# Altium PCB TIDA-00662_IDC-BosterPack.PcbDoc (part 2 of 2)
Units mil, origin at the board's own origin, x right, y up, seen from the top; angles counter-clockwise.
Board outline 2854.33 x 3248.03 mil, 4 copper layers (Top Layer, GND, +3.3V_Supply, Bottom Layer), stack 35.6 mil thick; 124 components, 110 nets, 427 pads, 203 vias.
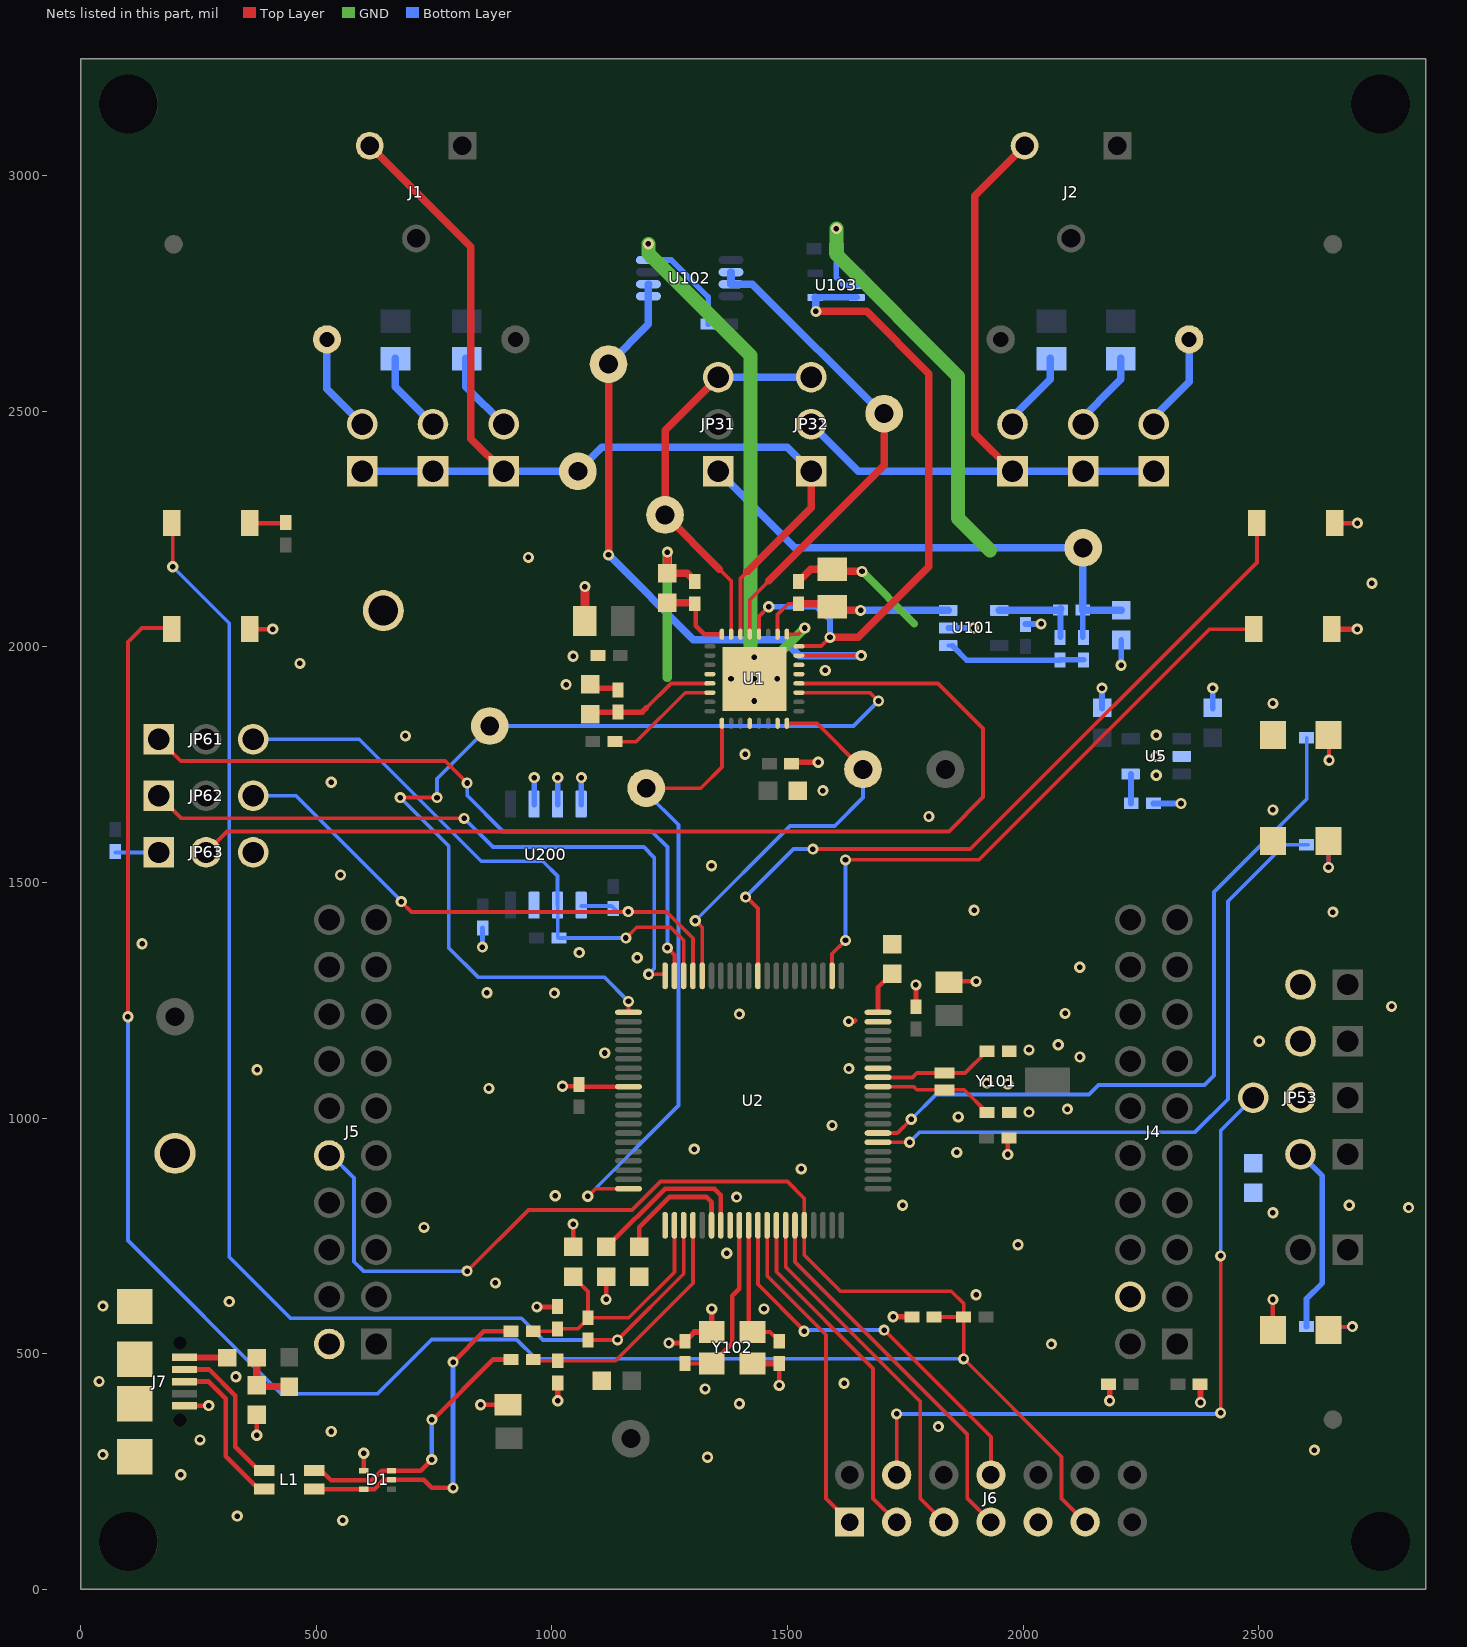
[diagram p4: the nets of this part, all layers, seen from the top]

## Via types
v1: diameter 23.62, hole 11.81, Top Layer to Bottom Layer, 200 vias
v2: diameter 23.62, hole 11.81, Top Layer to Bottom Layer, tented top, 2 vias
v3: diameter 23.62, hole 11.81, Top Layer to Bottom Layer, tented bottom, 1 vias

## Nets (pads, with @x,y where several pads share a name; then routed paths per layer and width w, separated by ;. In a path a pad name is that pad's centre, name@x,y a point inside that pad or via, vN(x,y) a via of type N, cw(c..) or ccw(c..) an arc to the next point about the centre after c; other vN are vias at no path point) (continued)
GND: C21.2 C22.1 C23.1 C24.2 C25.1 C28.1 C100.1 C101.1 C102.1 C103.1 C104.1 C105.1 C106.1 C107.2 C108.1 C109.2 C110.2 C111.2 C112.1 C113.2 C200.1 C201.2 C202.2 C203.1 C204.1 C205.2 C206.2 C207.2 C208.1 C209.2 C210.2 C211.2 C212.1 C213.2 C214.1 C215.2 C216.1 C217.1 D1.4 GND1.1 GND2.1 J4.4 J5.2 J6.9 J7.5 J7.6 J7.7 J7.8 J7.9 JP63.3 LED1.1 LED2.1 LED3.1 R208.1 S1.2 S2.1 S3.2 U1.4 U1.7 U1.13 U1.14 U1.17 U1.28 U1.33 U2.14 U2.19 U2.49 U2.61 U2.68 U5.2 U101.2 U102.4 U103.2 U200.2 U200.3 U200.4 U200.7 Y102.2 Y102.4 | length 4963.6
  Top Layer w8: U1.17@1498.43,2026.77 1523.11,2026.77 v1(1536.34,2040)
  Top Layer w10: J7.5@219.86,389.51 v1(271.51,389.51) ; S3.2@358.27,2037.52 v1(407.48,2037.52) ; v1(373.3,326.7) C28.1@373.3,370.2 ; D1.4@600.47,251.68 v1(600.47,288.53) ; v1(848.43,391.43) C24.2@907,391.43 ; v1(968,599) 1010.82,599 C207.2@1011.58,599.76 ; v1(1022.37,1067.52) 1053.75,1067.52 C210.2@1057.37,1071.14 1061.94,1066.58 U2.49@1162.4,1066.58 ; R208.1@1045,726.5 v1(1045,775) ; C102.1@1081.3,1920.2 C102.1@1089.17,1912.32 ; v1(1115,615) C203.1@1115,663.5 ; C103.1@1136.3,1912.32 C103.1@1140,1908.62 ; v1@1250,522.52 1278.75,522.52 C214.1@1282.37,526.14 ; v1(1482.37,432.52) C213.2@1482.37,478.9 ; v1(1629.49,1205) 1641.11,1205 1643,1206.89 ; C211.2@1772.37,1232.52 C211.2@1772.37,1236.14 v1(1772.37,1282.52) ; C215.2@1842.37,1288.39 1843.98,1290 v1(1900,1290) ; v1(1967.37,922.52) 1967.37,955.28 C209.2@1969.61,957.52 ; LED3.1@2529.89,550 v1(2529.89,614.89) ; S1.2@2659.26,2262.52 v1(2709.51,2262.52)
  Top Layer w12: v1(1012.37,400) C206.2@1012.37,437.52 ; C102.1@1089.17,1912.32 C103.1@1136.3,1912.32 ; C214.1@1282.37,526.14 1302.21,545.98 Y102.4@1339.06,545.98 v1@1339.06,595 ; Y102.2@1425.68,479.06 1425.83,478.9 C213.2@1482.37,478.9 ; C100.1@1508.62,1755 v1(1565,1755) ; v1(1724,578.31) C205.2@1765.13,578.31 ; C215.2@1842.37,1288.39 C215.2@1843.24,1287.52 ; v1@2183.47,396.22 C217.1@2183.47,437.52 ; v1(2376.39,396.22) C216.1@2376.39,437.52 ; S2.1@2659.26,2037.52 v1(2709,2037.52)
  Top Layer w16: v1(1245,2201) C104.1@1245,2156.5 1287.13,2156.5 C105.1@1305,2138.62 ; C107.2@1523,2138.62 1549.38,2165 C106.1@1595,2165 ; C106.1@1595,2160 v1(1658,2160)
  Top Layer w20: C109.2@1070,2055 v1(1070,2128)
  GND w16: v1(1658,2160) 1769,2049
  GND w20: 1245,1935 v1(1245,2201) ; 1471.34,1975 v1(1536.34,2040)
  GND w30: v1(1204.77,2855.23) 1204.77,2834.61 1421,2618.38 1421,1986.54 v1(1429.54,1978) ; v1(1603.62,2887.62) 1603.62,2832.38 1862,2574 1862,2273 1930,2205
  Bottom Layer w10: v1(852.37,1362.63) C200.1@852.37,1403.9
  Bottom Layer w12: U200.2@962.37,1664.8 v1(962.37,1722.52) ; U200.3@1012.37,1664.8 v1(1012.37,1722.52) ; U200.4@1062.37,1664.8 v1(1062.37,1722.52) ; v1(1204.77,2855.23) U102.4@1204.77,2820.91 1253.09,2820.91 1331.38,2742.62 C110.2@1331.38,2685 ; v1(1603.62,2887.62) C111.2@1603.62,2845 1603.62,2783.9 1620,2767.52 U103.2@1646.66,2767.52 ; U101.2@1840.87,2040 v1(1895,2040) ; C113.2@2005,2048.62 v1(2038,2048.62) ; C22.1@2167.37,1869.02 v1(2167.37,1912.52) ; v1(2208,1961) C112.1@2208,2014.5 ; C21.2@2275.99,1667.52 v1(2335,1667.52) ; C23.1@2402.37,1869.02 v1(2402.37,1912.52)
  other v1: 556,146 332,155 212,243 1330,280 47,285.77 2618.11,295.28 253,317 531.5,334.65 1820,345 1397.64,393.7 2183.47,400 1325,425 1620,437 39,441 329,451 2060,520 1248,522.52 1339,595 1450,595 47,600.77 314.96,610.24 1900,625 880,650 1371,713 1989,731 728.35,767.72 2530,799 2818.16,810 1744,815 2692,815 1392,832 1007,835 1529,892 1859,927 1302,934 1594.49,984.25 1862.37,1002.52 2012.37,1012.52 2094,1019 866.14,1062.99 1967.37,1072.52 1923,1074 374.02,1102.36 1630,1105 2120.32,1129.57 1112,1138 2012.37,1144.58 2074.42,1155.47 2501,1163 1397.64,1220.47 2089,1222 2782,1237 1005,1265 862,1266 2120,1320 1181.1,1340.2 1058,1351 130,1370 2657.48,1437.01 1896,1441 551.18,1515.75 1338.58,1535.43 1800,1640 2530,1654 1575,1695 531.5,1712.6 2282.37,1767.52 1410,1772 688.98,1811.02 2282.37,1812.52 2530,1880 1429.54,1885 1030,1920 1380,1932.28 1429.54,1932.28 1478,1932.28 1580,1950 465,1965 1045,1980 2740,2135 950,2190
  other v2: 2282.37,1727.52
JTAG_TCK: J6.7 U2.75 | length 802
  Top Layer w8: U2.75@1515.75,772.28 1515.75,694.25 1881.58,328.42 1881.58,192.52 J6.7@1931.58,142.52
JTAG_TDI: J6.3 U2.73 | length 735.5
  Top Layer w8: U2.73@1476.38,772.28 1476.38,673.62 1681.58,468.42 1681.58,192.52 J6.3@1731.58,142.52
JTAG_TDO: J6.1 U2.72 | length 702.2
  Top Layer w8: U2.72@1456.69,772.28 1456.69,664.89 1581.58,540 1581.58,192.52 J6.1@1631.58,142.52
JTAG_TMS: J6.5 U2.74 | length 768.7
  Top Layer w8: U2.74@1496.06,772.28 1496.06,683.94 1781.58,398.42 1781.58,192.52 J6.5@1831.58,142.52
JTAG_TST: J6.8 U2.71 | length 834.2
  Top Layer w8: U2.71@1437.01,772.28 1437.01,647.06 1535,549.06 v1(1535,547.52) ; v1(1705,550) 1931.58,323.42 J6.8@1931.58,242.52
  Bottom Layer w8: v1@1537.48,550 v1(1705,550)
JTAG_VCC_SENSE: J6.4 JP53.3 | length 1516.9
  Top Layer w8: J6.4@1731.58,242.52 v1@1731.58,368.42 ; v1(2419.21,374.21) v1(2419.21,707.52)
  Bottom Layer w8: v1(1731.58,372) v1@2417,372 ; v1@2415,370 v1@2417,372 ; v1(2419.21,374.21) v1@2417,372 ; v1(2419.21,707.52) 2419.21,973.7 JP53.3@2488.58,1043.07 ; JP53.3@2490.95,1043.07 JP53.3@2492.37,1041.65
LOL: J1.3 JP11.1 JP12.1 JP13.1 JP32.1 LOL.1 U1.22 | length 2196.8
  Top Layer w8: JP13.1@897.37,2372.52 JP13.1@897.57,2372.32 ; U1.22@1400.01,2026.77 1400.01,2145.01 1415,2160
  Top Layer w16: J1.3@613.16,3063.58 828,2848.74 828,2441.89 JP13.1@897.37,2372.52 ; 1415,2160 1550.01,2295.01 JP32.1@1550.01,2372.52
  Bottom Layer w16: JP11.1@611.19,2372.72 JP12.1@761.19,2372.72 ; JP12.1@762.37,2372.52 JP13.1@897.37,2372.52 LOL.1@1055,2372.52 1106,2423.52 1499.01,2423.52 JP32.1@1550.01,2372.52
LOR: JP31.3 JP32.3 LOR.1 U1.23 | length 847.6
  Top Layer w8: 1355,2165 1380.32,2139.68 U1.23@1380.32,2026.77
  Top Layer w16: JP31.3@1353.16,2572.52 1240,2459.36 LOR.1@1240,2280 1355,2165
  Bottom Layer w16: JP31.3@1353.16,2572.52 JP32.3@1550.01,2572.52
MCU_MCLK: MCLK.1 U1.1 U2.60 | length 1339
  Top Layer w8: v1(1076,834) 1092.04,850.04 U2.60@1162.4,850.04 ; MCLK.1@1200,1700 1315.64,1700 1360.64,1745 U1.1@1360.64,1837.8
  Bottom Layer w8: v1(1076,834) 1268.26,1026.26 1268.26,1622.26 1200,1690.52 MCLK.1@1200,1700
MCU_RST: C205.1 J5.10 J6.11 R202.1 S3.1 U2.76 | length 5789.7
  Top Layer w8: v1(100,1215) 100,2010 130,2040 190.43,2040 S3.1@192.91,2037.52 ; v1(820,675) 950,805 1170,805 1230,865 1499.89,865 1535.43,829.46 U2.76@1535.43,772.28 1535.43,709.46 1612.37,632.52 1847.37,632.52 1873.75,606.14 R202.1@1873.75,577.52 ; C205.1@1810.99,577.52 R202.1@1873.75,577.52 ; J6.11@2131.58,142.52 2081.58,192.52 2081.58,281.06 v1(1873.75,488.9) R202.1@1873.75,577.52
  Bottom Layer w8: v1(100,1215) 100,740 425,415 630,415 745,530 924.8,530 965.91,488.9 v1(1873.75,488.9) ; J5.10@529.54,922.99 580,872.53 580,695 600,675 v1(820,675)
MCU_SCL: JP61.3 R201.1 U2.38 U200.6 | length 1257.3
  Top Layer w8: v1(1157,1382) 1180,1405 1251.52,1405 1279.53,1376.99 U2.38@1279.53,1301.81
  Bottom Layer w8: JP61.3@365.75,1803.86 591.14,1803.86 850,1545 980.52,1545 1012,1513.52 U200.6@1012,1451.72 ; R201.1@1012.37,1382.52 U200.6@1012.37,1450.24 ; R201.1@1014.62,1382 v1(1157,1382)
MCU_SDA: JP62.3 R200.1 U2.37 U200.5 | length 1244.6
  Top Layer w8: v1(680,1459.17) 701.79,1437.38 1243.56,1437.38 1299.21,1381.72 U2.37@1299.21,1301.81
  Bottom Layer w8: JP62.3@365.75,1683.78 456.96,1683.78 680,1460.74 v1(680,1459.17) ; U200.5@1062.37,1450.24 1126.03,1450.24 1138.89,1437.38 1139.51,1438 v1(1162,1438)
NetC21_1: C21.1 U5.4 | length 62.8
  Bottom Layer w12: U5.4@2228.24,1730.12 2228.75,1729.6 C21.1@2228.75,1667.52
NetC25_2: C25.2 JP1.2 JP51.2 JP52.2 JP53.2 R20.1 | length 409.8
  Bottom Layer w12: JP1.2@2590.95,922.99 JP1.2@2588.58,922.99 2635,876.58 2635,650 2601.38,616.38 R20.1@2601.38,557.19 ; JP53.2@2590.95,1034.61 JP53.2@2590.95,1043.07
NetC28_2: C28.2 L2.2 L3.1 | length 135.4
  Top Layer w10: C28.2@373.37,431.52 C28.2@374.39,430.5
  Top Layer w15: C28.2@373.37,431.52 L2.2@373.37,496.52 ; C28.2@374.39,430.5 L3.1@443.37,430.5
NetC102_2: C102.2 C103.2 U1.29 | length 280.8
  Top Layer w8: 1200,1870.08 1252.36,1922.44 U1.29@1335.05,1922.44
  Top Layer w12: C102.2@1081.3,1857.2 1085.47,1861.38 C103.2@1140,1861.38 1191.3,1861.38 1200,1870.08
NetC104_2: C104.2 C105.2 U1.24 | length 170.4
  Top Layer w10: C105.2@1305,2091.38 1305,2045 1323.23,2026.77 U1.24@1360.64,2026.77
  Top Layer w12: C105.2@1302.87,2093.5 C105.2@1305,2091.38
  Top Layer w16: C104.2@1245,2093.5 C105.2@1302.87,2093.5
NetC106_2: C106.2 C107.1 U1.18 U101.3 | length 419.1
  Top Layer w8: U1.18@1478.75,2026.77 1478.75,2068.75 1501.38,2091.38 C107.1@1525,2091.38
  Top Layer w12: C106.2@1588.62,2091.38 C106.2@1595,2085
  Top Layer w16: C107.1@1525,2091.38 C106.2@1588.62,2091.38 ; C106.2@1593.62,2081.38 1597.6,2077.4 v1(1655,2077.4)
  Bottom Layer w16: v1(1655,2077.4) U101.3@1840.87,2077.4
NetC112_2: C112.2 JP31.1 R100.1 R106.1 VRef.1 | length 1114.4
  Bottom Layer w8: R100.1@2126.62,2021 R100.1@2128,2019.62
  Bottom Layer w12: R100.1@2126.62,2021 R106.1@2126.62,2078
  Bottom Layer w16: JP31.1@1353.16,2372.52 1515.68,2210 VRef.1@2127.37,2210 2126.62,2209.25 R106.1@2126.62,2078 2207.5,2078 C112.2@2208,2077.5
NetC114_1: C114.1 R106.2 U101.4 | length 193.7
  Bottom Layer w8: C114.1@2078,2019.62 C114.1@2079.38,2021
  Bottom Layer w12: C114.1@2079.38,2021 R106.2@2079.38,2081
  Bottom Layer w16: U101.4@1949.13,2077.4 2075.78,2077.4 R106.2@2079.38,2081
NetC114_2: C114.2 R100.2 U101.1 | length 300.1
  Bottom Layer w8: U101.1@1840.87,2002.6 U101.1@1849.4,2002.6
  Bottom Layer w12: U101.1@1849.4,2002.6 1880.62,1971.38 C114.2@2078,1971.38 ; C114.2@2078,1972.38 R100.2@2128,1972.38
NetC201_1: C201.1 U2.12 Y101.2 | length 254
  Top Layer w8: U2.12@1691.93,1066.58 1767.53,1066.58 1774.26,1059.84 Y101.2@1833.16,1059.84 1874.86,1059.84 C201.1@1923.12,1011.58
NetC202_1: C202.1 U2.13 Y101.1 | length 254.1
  Top Layer w8: U2.13@1691.93,1086.26 1765.32,1086.26 1774.34,1095.28 Y101.1@1833.16,1095.28 1876.82,1095.28 C202.1@1923.12,1141.58
NetC203_2: C203.2 U2.67 | length 362.8
  Top Layer w10: C203.2@1116.5,726.5 1240,850 1344.83,850 1358.27,836.56 U2.67@1358.27,772.28
NetC204_2: C204.2 U2.20 | length 96.9
  Top Layer w10: U2.20@1691.93,1224.06 1691.93,1277.08 1712.37,1297.52 C204.2@1727.37,1297.52
NetC206_1: C206.1 R206.1 U2.64 | length 531.3
  Top Layer w8: R206.1@960.21,487.52 962.96,484.76 1134.61,484.76 1299.21,649.36 U2.64@1299.21,772.28
NetC207_1: C207.1 R204.1 R205.2 R208.2 U2.62 | length 551.4
  Top Layer w8: R204.1@960.21,547.52 1006.58,547.52 C207.1@1011.58,552.52 1054.52,552.52 1078,576 1163,576 1259.84,672.84 U2.62@1259.84,772.28 ; R208.2@1045,663.5 1076.58,631.92 R205.2@1076.58,576.14
NetC208_2: C208.2 U2.66 | length 275.5
  Top Layer w10: C208.2@1185,726.5 1185,767.99 1249.53,832.52 1327.37,832.52 1338.58,821.31 U2.66@1338.58,772.28
NetC213_1: C213.1 U2.70 Y102.3 | length 294.7
  Top Layer w8: Y102.3@1425.68,545.98 1462.53,545.98 C213.1@1482.37,526.14
  Top Layer w10: U2.70@1417.32,772.28 1417.32,554.34 Y102.3@1425.68,545.98
NetC214_2: C214.2 U2.69 Y102.1 | length 374.2
  Top Layer w8: C214.2@1282.37,478.9 1282.53,479.06 Y102.1@1339.06,479.06
  Top Layer w10: Y102.1@1339.06,479.06 1382.37,522.36 1382.37,622.52 1397.64,637.79 U2.69@1397.64,772.28
NetCh1_1: Ch1.1 U1.15 U102.1 U102.2 | length 1367.6
  Top Layer w8: U1.15@1524.02,1981.5 v1(1656.5,1981.5)
  Top Layer w16: v1(1120,2195) Ch1.1@1120,2600
  Bottom Layer w16: v1(1120,2195) 1300,2015 1490.91,2015 1524.42,1981.5 v1(1656.5,1981.5) ; Ch1.1@1120,2600 1204.77,2684.77 U102.1@1204.77,2744.13 U102.2@1204.77,2769.72 U102.2@1205,2769.5
NetCh2_1: Ch2.1 U1.21 U102.6 U102.7 | length 1063.3
  Top Layer w8: U1.21@1419.69,2026.77 1419.69,2099.69 1460,2140
  Top Layer w16: 1460,2140 1705,2385 Ch2.1@1705,2495
  Bottom Layer w16: U102.6@1379.97,2795.32 U102.7@1379.97,2769.72 ; U102.7@1380.24,2770 U102.7@1379.97,2769.72 ; Ch2.1@1705,2480 1705,2490 1425.28,2769.72 U102.7@1379.97,2769.72
NetJ2_3: J2.3 JP21.1 JP22.1 JP23.1 JP32.2 | length 1528.9
  Top Layer w16: JP23.1@1977.37,2372.52 1897.37,2452.52 1897.37,2957.8 J2.3@2003.15,3063.58 ; J2.3@2008.15,3058.58 J2.3@2013.16,3063.58
  Bottom Layer w16: JP32.2@1550.01,2472.52 1650.01,2372.52 JP21.1@2262.37,2372.52
NetJ7_1: J7.1 L2.1 | length 92.7
  Top Layer w12: J7.1@219.86,491.87 312.36,491.87 L2.1@312.49,492
NetJ7_2: J7.2 L1.3 | length 322
  Top Layer w10: J7.2@219.86,466.28 272.72,466.28 328,411 328,301.89 377.68,252.21 L1.3@389.22,252.21
NetJ7_3: J7.3 L1.2 | length 335.3
  Top Layer w10: J7.3@219.86,440.69 271.31,440.69 307.37,404.63 307.37,282.52 377.05,212.84 L1.2@389.22,212.84
NetJP11_2: JP11.2 R101.2 | length 211.1
  Bottom Layer w16: R101.2@522.37,2652.52 522.37,2547.52 JP11.2@597.37,2472.52
NetJP12_2: JP12.2 R102.2 | length 173.1
  Bottom Layer w16: R102.2@667.37,2612.52 667.37,2552.52 JP12.2@747.37,2472.52
NetJP13_2: JP13.2 R103.2 | length 173.1
  Bottom Layer w16: R103.2@817.37,2612.52 817.37,2552.52 JP13.2@897.37,2472.52
NetJP21_2: JP21.2 R111.2 | length 217.3
  Bottom Layer w16: JP21.2@2262.37,2472.52 2352.37,2562.52 R111.2@2352.37,2652.52
NetJP22_2: JP22.2 R112.2 | length 179.4
  Bottom Layer w16: JP22.2@2112.37,2472.52 2207.37,2567.52 R112.2@2207.37,2612.52
NetJP23_2: JP23.2 R113.2 | length 179.4
  Bottom Layer w16: JP23.2@1962.37,2472.52 2057.37,2567.52 R113.2@2057.37,2612.52
NetJP63_1: JP63.1 R105.2 | length 92.9
  Bottom Layer w8: R105.2@73,1563.38 73.32,1563.7 JP63.1@165.75,1563.7
NetLED1_2: LED1.2 R203.1 | length 102
  Top Layer w8: LED1.2@2648,1813 2649.24,1811.76 v1(2649.24,1759.24)
  Bottom Layer w8: v1(2649.24,1759.24) R203.1@2649.24,1807
NetLED2_2: LED2.2 R207.1 | length 105.5
  Top Layer w8: v1(2648,1532) LED2.2@2648,1588
  Bottom Layer w8: v1(2648,1532) 2648,1576.38 R207.1@2651.62,1580
NetLED3_2: LED3.2 R20.2 | length 104
  Top Layer w8: LED3.2@2648,550 2655.19,557.19 v1(2698.81,557.19)
  Bottom Layer w8: R20.2@2648.62,557.19 v1(2698.81,557.19)
NetR104_2: R104.2 U1.30 | length 244.5
  Top Layer w8: R104.2@1133.62,1798.79 1178.79,1798.79 1282.76,1902.76 U1.30@1335.05,1902.76
NetR203_2: R203.2 U2.7 | length 1562.1
  Top Layer w8: U2.7@1691.93,968.15 1733,968.15 v1(1762.37,997.52)
  Bottom Layer w8: v1(1762.37,997.52) 1814.85,1050 2140,1050 2160,1070 2385,1070 2405,1090 2405,1480 2602,1677 R203.2@2602,1807
NetR205_1: R205.1 S4.1 U2.63 | length 2868.9
  Top Layer w8: S4.1@192.91,2262.52 195,2260.43 v1(195,2170) ; R205.1@1076.58,528.9 1138.9,528.9 v1(1139,529) 1279.53,669.53 U2.63@1279.53,772.28
  Bottom Layer w8: v1(195,2170) 315,2050 315,705 445,575 935,575 981,529 v1(1139,529)
NetR207_2: R207.2 U2.6 | length 1420.1
  Top Layer w8: U2.6@1691.93,948.47 v1(1759.11,948.47)
  Bottom Layer w8: v1(1759.11,948.47) 1780.64,970 2365,970 2435,1040 2435,1460 2555,1580 R207.2@2604.38,1580
NetR209_1: R209.1 S4.2 | length 77.2
  Top Layer w10: S4.2@358.27,2262.52 433.9,2262.52 R209.1@435,2263.62
NetS1_1: S1.1 U2.30 | length 1641.8
  Top Layer w8: v1(1411,1469) 1413,1469 1437.01,1444.99 U2.30@1437.01,1301.81 ; v1(1553.81,1570.81) 1887.81,1570.81 2496.06,2179.06 S1.1@2496.06,2262.52
  Bottom Layer w8: v1(1411,1469) 1512.81,1570.81 v1(1553.81,1570.81)
NetS2_2: S2.2 U2.22 | length 1331.7
  Top Layer w8: U2.22@1594.49,1301.81 1594.49,1348.49 v1(1623,1377) ; v1(1623,1548) 1906.05,1548 2343.46,1985.41 ; 2343.46,1985.46 2395.52,2037.52 S2.2@2493.91,2037.52
  Bottom Layer w8: v1(1623,1377) v1(1623,1548)
NetU1_16: U1.16 U1.20 U103.3 U103.4 | length 1407.6
  Top Layer w8: U1.20@1439.38,2026.77 1439.38,2064.38 v1(1460,2085) ; U1.16@1530.57,2001.55 1571.55,2001.55 v1(1590,2020)
  Top Layer w16: v1(1560,2712) 1668,2712 1800,2580 1800,2170 1650,2020 v1(1590,2020)
  Bottom Layer w12: v1(1460,2085) 1561.69,2085 1590,2056.69 v1(1590,2020)
  Bottom Layer w14: U103.4@1558.08,2741.93 U103.3@1646.66,2741.93
  Bottom Layer w16: U103.4@1558.71,2741.41 1560,2740.12 v1(1560,2712)
SPI_MISO: MISO.1 U1.11 U2.41 | length 2111.7
  Top Layer w8: v1(678,1680) v1(756,1680) ; v1(1162.37,1247.52) 1162.37,1228.98 U2.41@1164.77,1226.57 ; U1.11@1524.02,1902.76 1675.24,1902.76 v1(1693,1885)
  Bottom Layer w8: v1(678,1680) 781,1577 781,1361 843,1299 1110.89,1299 v1(1162.37,1247.52) ; v1(756,1680) 756,1720 MISO.1@868,1832 1640,1832 v1(1693,1885)
SPI_MOSI: JP62.1 U2.40 | length 1393.7
  Top Layer w8: JP62.1@165.75,1683.78 213.53,1636 v1(813.61,1636) ; v1(1205,1305) 1239.49,1305 U2.40@1240.16,1304.33
  Bottom Layer w8: v1(813.61,1636) 874.61,1575 1195,1575 1216.81,1553.19 1216.81,1316.81 v1(1205,1305)
SPI_SCLK: SCLK.1 U1.8 U2.36 | length 849.2
  Top Layer w8: v1(1304.19,1418.81) 1318.9,1404.1 U2.36@1318.9,1301.81 ; U1.8@1498.43,1837.8 1562.2,1837.8 SCLK.1@1660,1740
  Bottom Layer w8: v1(1304.19,1418.81) 1505.38,1620 1600,1620 1660,1680 SCLK.1@1660,1740
SPI_SELECT: JP63.2 U1.12 | length 2274.3
  Top Layer w8: JP63.2@265.75,1563.7 310.43,1608.38 1842.38,1608.38 1915,1681 1915,1827 1819.56,1922.44 U1.12@1524.02,1922.44
SPI_SS~: JP61.1 U2.39 | length 1469
  Top Layer w8: JP61.1@165.75,1803.86 212.09,1757.52 773.48,1757.52 v1(820,1711) ; v1(1245,1361) 1259.84,1346.16 U2.39@1259.84,1301.81
  Bottom Layer w8: v1(820,1711) 820,1684.42 896.04,1608.38 1211.62,1608.38 1245,1575 v1(1245,1361)
USB_DATA+: D1.2 D1.5 L1.1 R204.2 | length 738.3
  Top Layer w10: L1.1@506.84,212.84 L1.1@495.52,212.84 496.04,212.31 D1.5@600.47,212.31 623.31,212.31 643,232 D1.2@659.53,232 728,232 745,215 v1(790,215) ; v1(790,482) 855.52,547.52 R204.2@912.96,547.52
  Bottom Layer w10: v1(790,215) v1(790,482)
USB_DATA-: D1.3 L1.4 R206.2 | length 582.2
  Top Layer w10: L1.4@495.52,252.21 509.79,252.21 531,231 618,231 638.68,251.68 D1.3@659.53,251.68 721.54,251.68 v1(744.85,275) ; v1(745,360) 747.48,360 875,487.52 R206.2@912.96,487.52
  Bottom Layer w10: v1(744.85,275) 744.85,359.85 v1(745,360)
pads on no net: FID1.1 FID2.1 FID3.1 J6.6 J6.10 J6.12 J6.13 J6.14 J7.4 J7.MH1 J7.MH2 U1.2 U1.3 U1.5 U1.19 U1.25 U1.27 U2.5 U2.8 U2.9 U2.10 U2.15 U2.26 U2.32 Y101.
copper on no net:
  other v1: 1062.37,377.52

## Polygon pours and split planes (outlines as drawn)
GND on Bottom Layer "U103_GND" (solid, remove dead copper, pour order 14): 1616.99,2920 1584,2920 1571,2907 1571,2899 1571,2760 1588,2743 1589,2742 1683,2742 1697,2756 1698,2757 1698,2783 1683.48,2797.52 1630.37,2797.52 1630.37,2886.28 1630.37,2907
GND on Bottom Layer "U102_GND" (solid, remove dead copper, pour order 13): 1165,2882 1153,2870 1153,2819 1170,2802 1245,2802 1279,2768 1279,2669 1296,2652 1346,2652 1362.68,2668.68 1362.68,2750.23 1362.68,2760.32 1241,2882
GND on Bottom Layer "BotLayer_GND" (solid, remove dead copper, pour order 22): 19.68,2322.84 19.68,196.85 196.85,196.85 196.85,19.68 2657.48,19.68 2657.48,196.85 2834.65,196.85 2834.65,2322.83 1992.83,2322.83 1640,1970 1493,1970 1493,1995 1358,1995 1358,1955 1180,1955 1120,2015 1120,2130 927.16,2322.84
+5V_USB on Bottom Layer "+5V_USB" (solid, remove dead copper, pour order 17): 2477.37,1700 2317.37,1700 2317.37,1712.52 2317.37,1847.52 2477.37,1847.52
+3.3V_LDO on Bottom Layer "+3.3V_LDO" (solid, remove dead copper, pour order 18): 2247.37,1847.52 2247.37,1722.52 2062.37,1722.52 2062.37,1847.52
NetC25_2 on Bottom Layer "+3.3V_BottomLayer" (solid, remove dead copper, pour order 16): 2560,1345 2550.35,1345 2537,1331.64 2537,1016.02 2504.98,984 2464,984 2441.33,961.33 2441.33,948.67 2441.33,904.09 2441.33,883.67 2460,865 2615,865 2640,889.84 2641.81,891.65 2641.81,1330 2626.81,1345
GND on GND "GNDLayer" (solid, remove dead copper, pour order 23): 19.68,2322.83 19.68,196.85 196.85,196.85 196.85,19.68 2657.48,19.68 2657.48,196.85 2834.65,196.85 2834.65,2322.83 1992.83,2322.83 1640,1970 1500,1970 1500,2005 1360,2005 1360,1955 1180,1955 1120,2015 1120,2130 1096,2154 927.17,2322.83
+3.3V_SUPPLY on +3.3V_Supply "+3.3V_Supply" (solid, remove dead copper, pour order 24): 19.68,2322.83 19.68,196.85 196.85,196.85 196.85,19.68 2657.48,19.68 2657.48,196.85 2834.65,196.85 2834.65,2322.83 1995.31,2322.83 1995,2322.52 1642.48,1970 1640,1970 1515,1970 1510,1975 1510,2010 1365,2010 1360,2005 1360,1955 1180,1955 1120,2015 1120,2130 1120,2130.2 927.68,2322.52
NetC25_2 on +3.3V_Supply "+3.3V Selection" (solid, remove dead copper, pour order 15): 2527.96,1323.39 2527.96,869.65 2550.09,847.52 2617.37,847.52 2627.37,847.52 2647.37,867.52 2647.37,1327.52 2629.89,1345 2549.57,1345
GND on Top Layer "TopLayer_GND" (solid, remove dead copper, pour order 21): 19.98,2322.83 928.16,2322.84 1105,2146 1120,2131 1120,2015 1180,1955 1350,1955 1350,2010 1510,2010 1510,1970 1640,1970 1992.83,2322.83 2834.64,2322.84 2834.63,196.85 2657.47,196.85 2657.47,19.68 196.84,19.68 196.84,196.85 19.68,196.85

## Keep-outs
Keep-Out Layer:
  lines w10: -5,0 ccw(c0,0) 0,-5 ; -5,0 ccw(c0,0) 0,-5 ; -5,0 -5,3248.03 ; -5,3248.03 cw(c0,3248.03) 0,3253.03 ; -5,3248.03 cw(c0,3248.03) 0,3253.03 ; 0,-5 2854.33,-5 ; 0,3253.03 2854.33,3253.03 ; 2854.33,-5 ccw(c2854.33,0) 2859.33,0 ; 2854.33,-5 ccw(c2854.33,0) 2859.33,0 ; 2854.33,3253.03 cw(c2854.33,3248.03) 2859.33,3248.03 ; 2854.33,3253.03 cw(c2854.33,3248.03) 2859.33,3248.03 ; 2859.33,0 2859.33,3248.03
  text ".Layer_Name" at 577,-858.49 h60

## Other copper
Top Layer:
  text ".Layer_Name" at 577,-858.49 h60
Bottom Layer:
  text ".Layer_Name" at 577,-858.49 h60

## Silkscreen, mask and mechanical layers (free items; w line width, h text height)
Top Overlay:
  drawing of 1651 lines, arcs and shapes, not listed
  text "Z-Domain Booster Pack" at 1836,3131 h40 r180
  text "V1.0" at 1279,3053 h40 r180
  text "TIDA-00662" at 1730,3053 h40 r180
  text "SCL/SS" at 603,1818 h30 r180
  text "SDA/MOSI" at 651,1696 h30 r180
  text "I2C/SPI" at 616,1578 h30 r180
  text ".Layer_Name" at 577,-858.49 h60
Bottom Overlay:
  text ".Layer_Name" at 577,-858.49 h60
Top Paste:
  text ".Layer_Name" at 577,-858.49 h60
Bottom Paste:
  text ".Layer_Name" at 577,-858.49 h60
Top Solder:
  text ".Layer_Name" at 577,-858.49 h60
  text ".Layer_Name" at 577,-858.49 h60
Bottom Solder:
  text ".Layer_Name" at 577,-858.49 h60
Drill Guide:
  text ".Layer_Name" at 577,-858.49 h60
M1 Board Outline:
  the board outline again, w10
  text ".Layer_Name" at 577,-858.49 h60
M2 Board Dimensions:
  rectangle: 125,-400 500,-275
  rectangle: 0,-275 125,-150
  lines w3.94: 2.37,2.52 2.37,3250.55 2856.7,3250.55 2856.7,2.52 2.37,2.52
  lines w7: 0,-275 1000,-275 ; 125,-400 125,-150 ; 250,-400 250,-150 ; 500,-400 500,-150 ; 750,-400 750,-150 ; 0,-400 0,-150 1000,-150 1000,-400 0,-400
  text ".Layer_Name" at 577,-858.49 h60
M3 3D STEP Top:
  text ".Layer_Name" at 577,-858.49 h60
M4 3D STEP Bottom:
  text ".Layer_Name" at 577,-858.49 h60
M5 Assembly Top:
  lines w10: -292,-930.17 6308,-930.17 ; -292,-726.83 6310,-726.83 ; -292,-523.5 -292,-1133.5 3713,-1133.5 6310,-1133.5 6310,-523.5 -291.5,-523.5 -291.5,-1133.5 1284,-1133.5 ; 2173,-1133.5 2173,-523.5 ; 3440,-726.83 3440,-523.5 ; 4280,-726.83 4280,-523.5 ; 4902,-1140 4902,-937.17
  text "COMPONENTS MARKED 'DNP' SHOULD NOT BE POPULATED." at 1153.5,-318.5 h60
  text "ASSEMBLY VARIANT:" at 1153,-434 h60
  text ".VariantName" at 2189,-434 h60
  text "PCB VIEWED FROM TOP SIDE" at -228.5,-655.67 h60
  text "BOARD #:" at 2248,-655.67 h60
  text ".PRJ_Number" at 2793.5,-655.67 h60
  text "REV:" at 3638,-655.67 h60
  text ".PCB_Rev" at 3929.5,-655.67 h60
  text "SVN REV:" at 4476,-655.67 h60
  text ".VersionControl_RevNumber" at 4982,-655.67 h60
  text "TID #:" at 2248,-859 h60
  text ".TID" at 2793.5,-859 h60
  text "PLOT NAME =" at -228.5,-1064.34 h60
  text ".plot_File_Name" at 577,-1064.34 h60
  text "GENERATED    :" at 2250,-1064.34 h60
  text ".Print_Date" at 3119.5,-1064.34 h60
  text ".Print_Time" at 3848.5,-1064.34 h60
  text "TEXAS INSTRUMENTS" at 5113,-1064.34 h60
M6 Assembly Bottom:
  lines w10: -292.5,-727.33 6309.5,-727.33 ; -290.5,-930.67 6309.5,-930.67 ; 1115.5,-1140.5 1115.5,-937.67 ; 1737.5,-727.33 1737.5,-524 ; 2577.5,-727.33 2577.5,-524 ; 3844.5,-1134 3844.5,-524 ; 4733.5,-1134 6309,-1134 6309,-524 -292.5,-524 -292.5,-1134 2304.5,-1134 6309.5,-1134 6309.5,-524
  text "COMPONENTS MARKED 'DNP' SHOULD NOT BE POPULATED." at 6102,-318 h60
  text ".VariantName" at 5058,-434 h60
  text "ASSEMBLY VARIANT:" at 6097,-434 h60
  text ".VersionControl_RevNumber" at 1035.5,-656.17 h60
  text "SVN REV:" at 1541.5,-656.17 h60
  text ".PCB_Rev" at 2088,-656.17 h60
  text "REV:" at 2379.5,-656.17 h60
  text ".PRJ_Number" at 3224,-656.17 h60
  text "BOARD #:" at 3769.5,-656.17 h60
  text "PCB VIEWED FROM BOTTOM SIDE" at 6246,-656.17 h60
  text ".TID" at 3224,-859.5 h60
  text "TID #:" at 3769.5,-859.5 h60
  text "TEXAS INSTRUMENTS" at 904.5,-1064.84 h60
  text ".Print_Time" at 2169,-1064.84 h60
  text ".Print_Date" at 2898,-1064.84 h60
  text "GENERATED    :" at 3767.5,-1064.84 h60
  text ".plot_File_Name" at 5440.5,-1064.84 h60
  text "PLOT NAME =" at 6246,-1064.84 h60
M9 Title Sheet:
  drawing of 57 lines, arcs and shapes, not listed
  text "1" at 739.84,8036.5 h70
  text "2" at 3235.5,8036.5 h70
  text "3" at 5724.84,8036.5 h70
  text "4" at 8231.51,8036.5 h70
  text "5" at 10730.5,8036.5 h70
  text "6" at 13235.5,8036.5 h70
  text "A" at -416.5,6893.5 h70
  text "A" at 14383.5,6893.5 h70
  text "B" at -416.5,4513.5 h70
  text "B" at 14383.5,4513.5 h70
  text "C" at -416.5,2138.5 h70
  text "C" at 14383.5,2138.5 h70
  text "PROJECT TITLE:" at 11343.5,277.5 h45
  text ".PRJ_Title" at 11393.5,144.17 h70
  text "DESIGNED FOR:" at 11343.5,-23.5 h45
  text ".PRJ_Customer" at 11393.5,-163.5 h70
  text "D" at -416.5,-231.5 h70
  text "D" at 14383.5,-231.5 h70
  text "FILE NAME:" at 11343.5,-323.5 h45
  text ".PCB_File_Name_No_Path" at 11393.5,-443.5 h70
  text "Texas Instruments (TI) and/or its licensors do not warrant the accuracy or completeness of this specification" at 6374,-605.34 h45
  text "ENGINEER:" at 11343.5,-613.5 h45
  text "LAYOUT BY:" at 12848.5,-613.5 h45
  text "or any information contained therein. TI and/or its licensors do not warrant that this design will meet" at 6329.01,-718 h45
  text ".PRJ_Engineer" at 11393.5,-768.49 h70
  text ".PCB_Layout" at 12899,-768.49 h70
  text "the specifications, will be suitable for your application or fit for any particular purpose, or will operate in" at 6329.01,-830.67 h45
  text ".Layer_Name" at 577,-858.49 h60
  text "ALTIUM DESIGNER VERSION:" at 12848.5,-923.5 h45
  text "an implementation. TI and/or its licensors do not warrant that the design is production worthy. You should" at 6329.01,-943.33 h45
  text "completely validate and test your design implementation to confirm the system functionality for your application." at 6374,-1056 h45
  text ".print_Scale" at 11393.5,-1056.83 h70
  text ".Application_BuildNumber" at 12899,-1056.83 h70
  text "1" at 739.84,-1263.5 h70
  text "2" at 3235.5,-1263.5 h70
  text "3" at 5724.84,-1263.5 h70
  text "4" at 8231.51,-1263.5 h70
  text "5" at 10730.5,-1263.5 h70
  text "6" at 13235.5,-1263.5 h70
M10 Fab Notes:
  drawing of 185 lines, arcs and shapes, not listed
  text "DESIGN INFORMATION" at 12381.02,5910 h60
  text "MIN. TRACK WIDTH:" at 11736.46,5730 h60
  text "8" at 12832.7,5730 h60
  text "MIL" at 12987.46,5730 h60
  text "MIN. CLEARANCE:" at 11736.46,5598 h60
  text "MIL" at 12987.46,5598 h60
  text "6" at 12835,5590 h60
  text "MIN. VIA PAD SIZE:" at 11736.46,5466 h60
  text "24" at 12802.71,5466 h60
  text "MIL" at 12987.46,5466 h60
  text "0.05mm (2MIL)" at 12431.46,5324.29 h60
  text "MINIMUM ANNULAR RING" at 11407.23,5320 h60
  text "EXTERNAL" at 13139.46,5320 h60
  text "PER" at 11607.23,5202 h60
  text "IPC-D-275 CLASS 2 LEVEL C" at 11827.23,5202 h60
  text "MIL, HOLES" at 13315.46,5089.71 h60
  text "+/-" at 12923,5089 h60
  text "+/-" at 13777,5089 h60
  text "REGISTRATION TOLERANCES:" at 11407.23,5084 h60
  text "METAL" at 12607,5084 h60
  text "5" at 13183.2,5084 h60
  text "12" at 14016.2,5084 h60
  text "MIL" at 14132.46,5084 h60
  text "MATERIAL:" at 11332.46,4874.54 h60
  text "FR-4 High Tg" at 12318.9,4734.21 h60
  text "FR-408" at 11753.46,4725.64 h60
  text "X" at 12165.46,4725.64 h60
  text "OTHER" at 13241.46,4725.64 h60
  text "62 MIL (1.6mm) +/-10%" at 12073.56,4562.92 h60
  text "THICKNESS:" at 11407.23,4558.64 h60
  text "X" at 11945.4,4558.64 h60
  text "OTHER" at 13358.46,4558.64 h60
  text "TOLERANCE:" at 11407.23,4400.64 h60
  text "X" at 12246.53,4400.64 h60
  text "ANSI IPC-6012 TYPE 3 CLASS 2" at 12433.48,4400.64 h60
  text "OTHER +/-" at 12433.46,4244.64 h60
  text "BOW & TWIST:" at 11407.23,4087.64 h60
  text "X" at 12246.53,4087.64 h60
  text "ANSI IPC-6012 TYPE 3 CLASS 2" at 12433.48,4087.64 h60
  text "OTHER +/-" at 12433.46,3929.13 h60
  text "DRILLING:" at 11332.46,3790.64 h60
  text "REFERENCE:" at 11407.23,3673.64 h60
  text "X" at 12055.46,3673.64 h60
  text "AS SHOWN" at 12242.46,3673.64 h60
  text "X" at 12956.46,3673.64 h60
  text "NC_DRILL FILES" at 13093.46,3673.64 h60
  text "PTH MIN COPPER THICKNESS:" at 11407.23,3515.64 h60
  text "X" at 12757.46,3515.64 h60
  text "1MIL" at 12894.46,3515.64 h60
  text "OTHER" at 13391.46,3515.64 h60
  text "BOARD FINISH:" at 11332.46,3356.64 h60
  text "SILKSCREEN:" at 11487.68,3238.64 h60
  text "X" at 12436.46,3238.64 h60
  text "TOP" at 12562.46,3238.64 h60
  text "X" at 12946.46,3238.64 h60
  text "BOTTOM" at 13073.46,3238.64 h60
  text "SILKSCREEN COLOR:" at 11487.68,3071.64 h60
  text "X" at 12435.42,3071.64 h60
  text "WHITE" at 12562.46,3071.64 h60
  text "OTHER" at 13073.46,3071.64 h60
  text "SOLDER RESIST COLOR:" at 11487.68,2901.64 h60
  text "X" at 12055.42,2742.44 h60
  text "GREEN" at 12182.46,2742.44 h60
  text "BLUE" at 12773.46,2742.44 h60
  text "OTHER" at 13311.46,2742.44 h60
  text "IMMERSION GOLD (ENIG)" at 12393.46,2553.92 h60
  text "ENEPIG" at 13731,2550.64 h60
  text "SURFACE FINISH:" at 11332.46,2549.64 h60
  text "X" at 12206.51,2549.64 h60
  text "IMM. TIN/SILVER OR EQUIV" at 11662,2392.64 h60
  text "OTHER" at 13093.46,2392.64 h60
  text "ARRAY/PANEL:" at 11332.46,2213.64 h60
  text "CUT AND TRIM PER MECH LAYER 1" at 12393.46,2209.35 h60
  text "N.C. ROUTE" at 12393.46,2057.64 h60
  text "X" at 13072.46,2057.64 h60
  text "V. SCORE" at 13259.46,2057.64 h60
  text "CERTIFICATION:" at 11332.46,1920.64 h60
  text "MATERIALS AND WORKMANSHIP FOR ALL PCBS" at 12057.46,1920.64 h60
  text "TO MEET OR EXCEED THE REQUIREMENTS OF:" at 12057.46,1822.64 h60
  text "X" at 11683.96,1686.13 h60
  text "ANSI IPC-A-600F CLASS ->" at 11822.96,1686.13 h60
  text "X" at 13462.02,1686.13 h60
  text "2" at 13580.96,1686.14 h60
  text "1" at 13265.96,1684.64 h60
  text "3" at 13934.96,1684.64 h60
  text "X" at 11686.02,1526.64 h60
  text "UL 94V-0" at 11822.96,1526.64 h60
  text "X" at 12498.02,1526.64 h60
  text "RoHS" at 12634.96,1526.64 h60
  text "OTHER" at 13279.36,1526.64 h60
  text "PER ORDER" at 13676.42,1526.64 h60
  text "ADDITIONAL REQUIREMENTS:" at 11332.46,1385.64 h60
  text "MICROSECTION:" at 11407.23,1270.64 h60
  text "YES" at 12312.96,1270.64 h60
  text "REQUIRED" at 13174.46,1114.49 h60
  text "BARE BOARD ELEC. TEST:" at 11407.23,1111.64 h60
  text "NONE" at 12712.96,1111.64 h60
  text "X" at 13047.46,1111.64 h60
  text "PER ORDER" at 13766.46,1111.64 h60
  text "MANUFACTURER'S UL:" at 11407.23,954.64 h60
  text "RAIL" at 12572.96,950.35 h60
  text "METAL" at 13064.77,950.35 h60
  text "X" at 13440,950 h60
  text "SILK" at 13576.46,950.35 h60
  text ".Layer_Name" at 577,-858.49 h60
M11 Gerber Information:
  lines w10: -292,-930.17 6308,-930.17 ; -292,-726.83 6310,-726.83 ; -292,-523.5 -292,-1133.5 3713,-1133.5 6310,-1133.5 6310,-523.5 -291.5,-523.5 -291.5,-1133.5 1284,-1133.5 ; 2173,-1133.5 2173,-523.5 ; 3440,-726.83 3440,-523.5 ; 4280,-726.83 4280,-523.5 ; 4902,-1140 4902,-937.17
  text "ALL ARTWORK VIEWED FROM TOP SIDE" at -228.5,-655.67 h60
  text "BOARD #:" at 2248,-655.67 h60
  text ".PRJ_Number" at 2793.5,-655.67 h60
  text "REV:" at 3638,-655.67 h60
  text ".PCB_Rev" at 3929.5,-655.67 h60
  text "SVN REV:" at 4476,-655.67 h60
  text ".VersionControl_RevNumber" at 4982,-655.67 h60
  text "LAYER NAME =" at -228.5,-858.49 h60
  text "TID #:" at 2248,-859 h60
  text ".TID" at 2793.5,-859 h60
  text "PLOT NAME =" at -228.5,-1064.34 h60
  text ".plot_File_Name" at 577,-1064.34 h60
  text "GENERATED    :" at 2250,-1064.34 h60
  text ".Print_Date" at 3119.5,-1064.34 h60
  text ".Print_Time" at 3848.5,-1064.34 h60
  text "TEXAS INSTRUMENTS" at 5113,-1064.34 h60
M12 Stackup:
  drawing of 373 lines, arcs and shapes, not listed
  text "Layer" at 6816.34,7751 h60
  text "Name" at 7226.26,7751 h60
  text "Material" at 8156,7751 h60
  text "Thickness" at 9015.77,7751 h60
  text "Constant" at 9665.6,7751 h60
  text "Board Layer Stack" at 10235.46,7751 h60
  text "1" at 6816.34,7631 h60
  text "Top Overlay" at 7226.26,7631 h60
  text "2" at 6816.34,7511 h60
  text "Top Solder" at 7226.26,7511 h60
  text "Solder Resist" at 8156,7511 h60
  text "0,40mil" at 9015.77,7511 h60
  text "3,5" at 9665.6,7511 h60
  text "3" at 6816.34,7391 h60
  text "Top Layer" at 7226.26,7391 h60
  text "Copper" at 8156,7391 h60
  text "1,40mil" at 9015.77,7391 h60
  text "4" at 6816.34,7271 h60
  text "Dielectric1" at 7226.26,7271 h60
  text "FR-4" at 8156,7271 h60
  text "5,00mil" at 9015.77,7271 h60
  text "4,2" at 9665.6,7271 h60
  text "5" at 6816.34,7151 h60
  text "Dielectric 6" at 7226.26,7151 h60
  text "FR-4" at 8156,7151 h60
  text "5,00mil" at 9015.77,7151 h60
  text "4,2" at 9665.6,7151 h60
  text "6" at 6816.34,7031 h60
  text "GND" at 7226.26,7031 h60
  text "Copper" at 8156,7031 h60
  text "1,40mil" at 9015.77,7031 h60
  text "7" at 6816.34,6911 h60
  text "Dielectric3" at 7226.26,6911 h60
  text "FR-4" at 8156,6911 h60
  text "5,00mil" at 9015.77,6911 h60
  text "4,2" at 9665.6,6911 h60
  text "8" at 6816.34,6791 h60
  text "Dielectric5" at 7226.26,6791 h60
  text "FR-4" at 8156,6791 h60
  text "5,00mil" at 9015.77,6791 h60
  text "4,2" at 9665.6,6791 h60
  text "9" at 6816.34,6671 h60
  text "+3.3V_Supply" at 7226.26,6671 h60
  text "Copper" at 8156,6671 h60
  text "1,40mil" at 9015.77,6671 h60
  text "10" at 6816.34,6551 h60
  text "Dielectric4" at 7226.26,6551 h60
  text "FR-4" at 8156,6551 h60
  text "5,00mil" at 9015.77,6551 h60
  text "4,2" at 9665.6,6551 h60
  text "11" at 6816.34,6431 h60
  text "Dielectric 8" at 7226.26,6431 h60
  text "FR-4" at 8156,6431 h60
  text "5,00mil" at 9015.77,6431 h60
  text "4,2" at 9665.6,6431 h60
  text "12" at 6816.34,6311 h60
  text "Bottom Layer" at 7226.26,6311 h60
  text "Copper" at 8156,6311 h60
  text "1,40mil" at 9015.77,6311 h60
  text "13" at 6816.34,6191 h60
  text "Bottom Solder" at 7226.26,6191 h60
  text "Solder Resist" at 8156,6191 h60
  text "0,40mil" at 9015.77,6191 h60
  text "3,5" at 9665.6,6191 h60
  text "14" at 6816.34,6071 h60
  text "Bottom Overlay" at 7226.26,6071 h60
  text ".Layer_Name" at 577,-858.49 h60
M13 Component Bodies Top:
  text ".Layer_Name" at 577,-858.49 h60
M14 Component Bodies Bottom:
  text ".Layer_Name" at 577,-858.49 h60
M15 Courtyards Top:
  text ".Layer_Name" at 577,-858.49 h60
M16 Courtyards Bottom:
  text ".Layer_Name" at 577,-858.49 h60
Drill Drawing:
  circle w10: c5236.62,4090.33 r33.33
  lines w10: 5203.29,3473.67 5219.96,3473.67 5236.62,3457 5253.29,3473.67 5269.96,3473.67 5253.29,3490.33 5269.96,3507 5253.29,3507 5236.62,3523.67 5219.96,3507 5203.29,3507 5219.96,3490.33 5203.29,3473.67 ; 5203.29,3607 5203.29,3623.67 5219.96,3640.33 5203.29,3657 5203.29,3673.67 5219.96,3673.67 5236.62,3657 5253.29,3673.67 5269.96,3673.67 5269.96,3657 5253.29,3640.33 5269.96,3623.67 5269.96,3607 5253.29,3607 5236.62,3623.67 5219.96,3607 5203.29,3607 ; 5203.29,3757 5269.96,3757 5269.96,3823.67 5203.29,3823.67 5203.29,3757 ; 5203.29,4223.67 5219.96,4223.67 5219.96,4207 5253.29,4207 5253.29,4223.67 5269.96,4223.67 5269.96,4257 5253.29,4257 5253.29,4273.67 5219.96,4273.67 5219.96,4257 5203.29,4257 5203.29,4223.67 ; 5203.29,4357 5236.62,4373.67 5269.96,4357 5253.29,4390.33 5269.96,4423.67 5236.62,4407 5203.29,4423.67 5219.96,4390.33 5203.29,4357 ; 5216.62,3480.33 5226.62,3480.33 5236.62,3470.33 5246.62,3480.33 5256.62,3480.33 5246.62,3490.33 5256.62,3500.33 5246.62,3500.33 5236.62,3510.33 5226.62,3500.33 5216.62,3500.33 5226.62,3490.33 5216.62,3480.33 ; 5216.62,3620.33 5216.62,3630.33 5226.62,3640.33 5216.62,3650.33 5216.62,3660.33 5226.62,3660.33 5236.62,3650.33 5246.62,3660.33 5256.62,3660.33 5256.62,3650.33 5246.62,3640.33 5256.62,3630.33 5256.62,3620.33 5246.62,3620.33 5236.62,3630.33 5226.62,3620.33 5216.62,3620.33 ; 5216.62,4230.33 5226.62,4230.33 5226.62,4220.33 5246.62,4220.33 5246.62,4230.33 5256.62,4230.33 5256.62,4250.33 5246.62,4250.33 5246.62,4260.33 5226.62,4260.33 5226.62,4250.33 5216.62,4250.33 5216.62,4230.33 ; 5216.62,4370.33 5236.62,4380.33 5256.62,4370.33 5246.62,4390.33 5256.62,4410.33 5236.62,4400.33 5216.62,4410.33 5226.62,4390.33 5216.62,4370.33
  lines w15: 5143.5,3262 8574.61,3262 ; 5143.5,4612 8574.61,4612 ; 5694.38,3112 5694.38,4762 ; 6294.22,3112 6294.22,4762 ; 7433.88,3112 7433.88,4762 ; 7939.76,3112 7939.76,4762 ; 5143.5,3112 8574.61,3112 8574.61,4762 5143.5,4762 5143.5,3112
  text "Symbol" at 5233.5,4657 h72
  text "Count" at 5739.38,4657 h72
  text "Hole Size" at 6339.22,4657 h72
  text "Plated" at 7478.88,4657 h72
  text "Via/Pad" at 7984.76,4657 h72
  text "2" at 5739.38,4507 h60
  text "27.56mil (0.700mm)" at 6339.22,4507 h60
  text "NPTH" at 7478.88,4507 h60
  text "Pad" at 7984.76,4507 h60
  text "B" at 5204.41,4497.01 h66.67
  text "2" at 5739.38,4357 h60
  text "63.00mil (1.600mm)" at 6339.22,4357 h60
  text "PTH" at 7478.88,4357 h60
  text "Pad" at 7984.76,4357 h60
  text "4" at 5739.38,4207 h60
  text "32.00mil (0.813mm)" at 6339.22,4207 h60
  text "PTH" at 7478.88,4207 h60
  text "Pad" at 7984.76,4207 h60
  text "4" at 5739.38,4057 h60
  text "125.00mil (3.175mm)" at 6339.22,4057 h60
  text "NPTH" at 7478.88,4057 h60
  text "Pad" at 7984.76,4057 h60
  text "6" at 5739.38,3907 h60
  text "39.37mil (1.000mm)" at 6339.22,3907 h60
  text "PTH" at 7478.88,3907 h60
  text "Pad" at 7984.76,3907 h60
  text "A" at 5204.41,3897.01 h66.67
  text "11" at 5739.38,3757 h60
  text "40.00mil (1.016mm)" at 6339.22,3757 h60
  text "PTH" at 7478.88,3757 h60
  text "Pad" at 7984.76,3757 h60
  text "14" at 5739.38,3607 h60
  text "37.00mil (0.940mm)" at 6339.22,3607 h60
  text "PTH" at 7478.88,3607 h60
  text "Pad" at 7984.76,3607 h60
  text "78" at 5739.38,3457 h60
  text "45.28mil (1.150mm)" at 6339.22,3457 h60
  text "PTH" at 7478.88,3457 h60
  text "Pad" at 7984.76,3457 h60
  text "203" at 5739.38,3307 h60
  text "11.81mil (0.300mm)" at 6339.22,3307 h60
  text "PTH" at 7478.88,3307 h60
  text "Via" at 7984.76,3307 h60
  text "C" at 5204.41,3297.01 h66.67
  text "324 Total" at 5739.38,3157 h60
  text ".Layer_Name" at 577,-858.49 h60

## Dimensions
0,0 to 2854.33,0 on M2 Board Dimensions
0,0 to 0,3248.03 on M2 Board Dimensions
0,-400 to 1000,-400 on M2 Board Dimensions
